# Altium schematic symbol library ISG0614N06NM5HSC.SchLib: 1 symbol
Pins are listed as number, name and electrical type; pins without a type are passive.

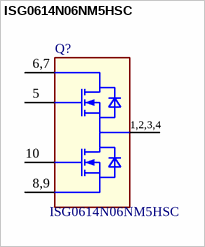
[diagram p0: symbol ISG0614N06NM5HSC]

## ISG0614N06NM5HSC
designator Q?
Small Signal Dual N-Channel Enhancement Transistor, Pin 1 Source, 2 Source, 3 Drain, 4 Drain, 5 Gate, 6 Drain, 7 Drain, 8 Source, 9 Source 10 Gate, 10 Pins; Manufacturer: Infineon Technologies
pins: 1 S1 "Q1 Source", 2 S2 "Q1 Source", 3 D1 "Q2 Drain", 4 D2 "Q2 Drain", 5 G1 "Q1 Gate", 6 D3 "Q1 Drain", 7 D4 "Q1 Drain", 8 S3 "Q2 Source", 9 S4 "Q2 Source", 10 G2 "Q2 Gate"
